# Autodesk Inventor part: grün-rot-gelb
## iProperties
Created: 2004-10
Part Number: grün-rot-gelb
Document SubType Name: Modeling
Designer: sahrens
Manufacturer: Standard
Standards Organization: Custom
Author: sahrens
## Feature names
1. Extrusion1
2. Rundung2 [Fillet]
